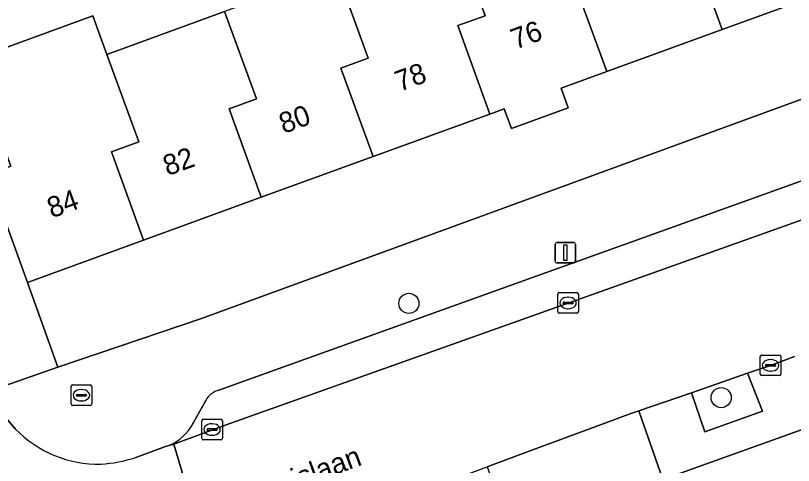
# Model space of a CAD drawing. Extents: x 162523 to 163266, y 381230 to 382050.
# Drawn here: x 162737.39 to 162775.21, y 381718.66 to 381740.55 of the extents above; entities that cross this region are included whole.
import ezdxf

# ---------------------------------------------------------------- set-up
doc = ezdxf.new("R2010")
doc.units = 0
for name, color, linetype in [('IMGEO_Boom', 7, 'Continuous'), ('IMGEO_Brandkraan', 7, 'Continuous'), ('IMGEO_Erf', 7, 'Continuous'), ('IMGEO_Groenvoorziening', 7, 'Continuous'), ('IMGEO_Kolk', 7, 'Continuous'), ('IMGEO_Lichtmast', 7, 'Continuous'), ('IMGEO_Openbare_ruimte_label', 7, 'Continuous'), ('IMGEO_Pand', 7, 'Continuous'), ('IMGEO_Pand_nummerreeks', 7, 'Continuous'), ('IMGEO_Parkeervlak_open', 7, 'Continuous'), ('IMGEO_Rijbaan_lokaal_open', 7, 'Continuous'), ('IMGEO_Voetpad_open', 7, 'Continuous')]:
    doc.layers.add(name, color=color, linetype=linetype)

msp = doc.modelspace()

# ---------------------------------------------------------------- linework, layer by layer
at = {"layer": 'IMGEO_Boom'}
for centre in [(162756.514, 381726.547), (162771.693, 381721.963)]:
    msp.add_circle(centre, 0.489, dxfattribs=at)
at = {"layer": 'IMGEO_Brandkraan'}
for p, q in [((162740.091, 381721.654), (162740.091, 381722.506)), ((162740.166, 381722.58), (162741.018, 381722.58)), ((162740.579, 381722.36), (162740.604, 381722.36)), ((162741.092, 381722.506), (162741.092, 381721.654)), ((162740.35, 381722.074), (162740.35, 381722.086)), ((162740.788, 381722.037), (162740.39, 381722.037)), ((162740.393, 381722.123), (162740.791, 381722.123)), ((162740.834, 381722.086), (162740.834, 381722.074)), ((162741.018, 381721.58), (162740.166, 381721.58)), ((162740.602, 381721.8), (162740.577, 381721.8))]:
    msp.add_line(p, q, dxfattribs=at)
for points in [[(162740.091, 381721.654), (162740.091, 381722.506)], [(162740.166, 381722.58), (162741.018, 381722.58)], [(162741.092, 381722.506), (162741.092, 381721.654)], [(162741.018, 381721.58), (162740.166, 381721.58)]]:
    msp.add_lwpolyline(points, dxfattribs=at)
for centre, radius, start, end in [((162740.168, 381722.504), 0.0765, 91.552, 178.448), ((162740.168, 381722.504), 0.0765, 91.552, 178.448), ((162741.016, 381722.504), 0.0765, 1.552, 88.448), ((162741.016, 381722.504), 0.0765, 1.552, 88.448), ((162740.39, 381722.083), 0.0403, 85.8775, 175.7526), ((162740.387, 381722.073), 0.0366, 178.938, 274.7102), ((162740.791, 381722.08), 0.043, 264.8664, 352.4533), ((162740.795, 381722.085), 0.0386, 1.7309, 96.639), ((162740.168, 381721.656), 0.0765, 181.552, 268.448), ((162740.168, 381721.656), 0.0765, 181.552, 268.448), ((162741.016, 381721.656), 0.0765, 271.552, 358.448), ((162741.016, 381721.656), 0.0765, 271.552, 358.448)]:
    msp.add_arc(centre, radius, start, end, dxfattribs=at)
for centre, major_axis, ratio, start_param, end_param in [((162740.578, 381722.08), (-0.387, 0.002), 0.722429, 4.712389, 7.853982), ((162740.603, 381722.08), (-0.39, 0.002), 0.717154, 1.570796, 4.712389)]:
    msp.add_ellipse(centre, major_axis=major_axis, ratio=ratio, start_param=start_param, end_param=end_param, dxfattribs=at)
at = {"layer": 'IMGEO_Erf'}
msp.add_lwpolyline([(162784.426, 381739.706), (162784.481, 381739.514), (162785.552, 381739.818), (162782.673, 381748.437), (162781.573, 381748.036), (162783.048, 381743.984), (162777.375, 381741.918), (162771.742, 381739.867), (162766.13, 381737.823), (162763.908, 381737.014), (162764.256, 381736.059), (162761.495, 381735.05), (162761.145, 381736.008), (162760.453, 381735.756), (162754.777, 381733.689), (162749.334, 381731.706), (162743.616, 381729.624), (162737.973, 381727.569), (162739.44, 381723.44), (162746.424, 381725.819)], close=True, dxfattribs=at)
for points in [[(162731.305, 381742.815), (162726.488, 381738.887), (162729.198, 381735.639), (162730.444, 381734.146), (162736.062, 381736.232), (162735.275, 381738.394), (162738.978, 381739.743), (162741.146, 381740.533), (162741.831, 381738.653), (162744.361, 381739.575), (162747.549, 381740.736)], [(162778.489, 381721.436), (162768.851, 381717.989), (162762.252, 381715.555), (162762.466, 381714.975), (162766.58, 381716.476), (162767.337, 381714.403), (162767.817, 381714.579), (162768.163, 381713.64), (162773.695, 381715.655), (162773.351, 381716.588), (162780.839, 381719.349)]]:
    msp.add_lwpolyline(points, dxfattribs=at)
at = {"layer": 'IMGEO_Groenvoorziening'}
msp.add_lwpolyline([(162770.249, 381722.202), (162770.895, 381720.292), (162773.711, 381721.304), (162772.973, 381723.146)], close=True, dxfattribs=at)
at = {"layer": 'IMGEO_Kolk'}
for p, q in [((162763.749, 381726.143), (162763.749, 381726.995)), ((162763.824, 381727.069), (162764.676, 381727.069)), ((162764.237, 381726.849), (162764.262, 381726.849)), ((162764.75, 381726.995), (162764.75, 381726.143)), ((162764.008, 381726.563), (162764.008, 381726.575)), ((162764.446, 381726.526), (162764.048, 381726.526)), ((162764.051, 381726.612), (162764.449, 381726.612)), ((162764.492, 381726.575), (162764.492, 381726.563)), ((162764.676, 381726.069), (162763.824, 381726.069)), ((162764.26, 381726.289), (162764.235, 381726.289)), ((162773.592, 381723.107), (162773.592, 381723.959)), ((162773.667, 381724.033), (162774.519, 381724.033)), ((162774.08, 381723.813), (162774.105, 381723.813)), ((162774.593, 381723.959), (162774.593, 381723.107)), ((162773.851, 381723.527), (162773.851, 381723.539)), ((162774.289, 381723.49), (162773.891, 381723.49)), ((162773.894, 381723.576), (162774.292, 381723.576)), ((162774.335, 381723.539), (162774.335, 381723.527)), ((162774.103, 381723.253), (162774.078, 381723.253)), ((162774.519, 381723.033), (162773.667, 381723.033)), ((162746.443, 381719.985), (162746.443, 381720.837)), ((162746.518, 381720.911), (162747.37, 381720.911)), ((162747.444, 381720.837), (162747.444, 381719.985)), ((162746.702, 381720.405), (162746.702, 381720.417)), ((162746.745, 381720.454), (162747.143, 381720.454)), ((162746.931, 381720.691), (162746.956, 381720.691)), ((162747.186, 381720.417), (162747.186, 381720.405)), ((162747.14, 381720.368), (162746.742, 381720.368)), ((162746.954, 381720.131), (162746.929, 381720.131)), ((162747.37, 381719.911), (162746.518, 381719.911))]:
    msp.add_line(p, q, dxfattribs=at)
for points in [[(162763.749, 381726.143), (162763.749, 381726.995)], [(162763.824, 381727.069), (162764.676, 381727.069)], [(162764.75, 381726.995), (162764.75, 381726.143)], [(162764.676, 381726.069), (162763.824, 381726.069)], [(162773.592, 381723.107), (162773.592, 381723.959)], [(162773.667, 381724.033), (162774.519, 381724.033)], [(162774.593, 381723.959), (162774.593, 381723.107)], [(162774.519, 381723.033), (162773.667, 381723.033)], [(162746.443, 381719.985), (162746.443, 381720.837)], [(162746.518, 381720.911), (162747.37, 381720.911)], [(162747.444, 381720.837), (162747.444, 381719.985)], [(162747.37, 381719.911), (162746.518, 381719.911)]]:
    msp.add_lwpolyline(points, dxfattribs=at)
for centre, radius, start, end in [((162763.826, 381726.993), 0.0765, 91.552, 178.448), ((162763.826, 381726.993), 0.0765, 91.552, 178.448), ((162764.674, 381726.993), 0.0765, 1.552, 88.448), ((162764.674, 381726.993), 0.0765, 1.552, 88.448), ((162764.048, 381726.572), 0.0403, 85.8775, 175.7526), ((162764.045, 381726.562), 0.0366, 178.938, 274.7102), ((162764.449, 381726.569), 0.043, 264.8664, 352.4533), ((162764.453, 381726.574), 0.0386, 1.7309, 96.639), ((162763.826, 381726.145), 0.0765, 181.552, 268.448), ((162763.826, 381726.145), 0.0765, 181.552, 268.448), ((162764.674, 381726.145), 0.0765, 271.552, 358.448), ((162764.674, 381726.145), 0.0765, 271.552, 358.448), ((162773.669, 381723.957), 0.0765, 91.552, 178.448), ((162773.669, 381723.957), 0.0765, 91.552, 178.448), ((162774.517, 381723.957), 0.0765, 1.552, 88.448), ((162774.517, 381723.957), 0.0765, 1.552, 88.448), ((162773.891, 381723.536), 0.0403, 85.8775, 175.7526), ((162773.888, 381723.526), 0.0366, 178.938, 274.7102), ((162774.292, 381723.533), 0.043, 264.8664, 352.4533), ((162774.296, 381723.538), 0.0386, 1.7309, 96.639), ((162773.669, 381723.109), 0.0765, 181.552, 268.448), ((162773.669, 381723.109), 0.0765, 181.552, 268.448), ((162774.517, 381723.109), 0.0765, 271.552, 358.448), ((162774.517, 381723.109), 0.0765, 271.552, 358.448), ((162746.52, 381720.835), 0.0765, 91.552, 178.448), ((162746.52, 381720.835), 0.0765, 91.552, 178.448), ((162747.368, 381720.835), 0.0765, 1.552, 88.448), ((162747.368, 381720.835), 0.0765, 1.552, 88.448), ((162746.742, 381720.414), 0.0403, 85.8775, 175.7526), ((162746.739, 381720.404), 0.0366, 178.938, 274.7102), ((162747.143, 381720.411), 0.043, 264.8664, 352.4533), ((162747.147, 381720.416), 0.0386, 1.7309, 96.639), ((162746.52, 381719.987), 0.0765, 181.552, 268.448), ((162746.52, 381719.987), 0.0765, 181.552, 268.448), ((162747.368, 381719.987), 0.0765, 271.552, 358.448), ((162747.368, 381719.987), 0.0765, 271.552, 358.448)]:
    msp.add_arc(centre, radius, start, end, dxfattribs=at)
for centre, major_axis, ratio, start_param, end_param in [((162764.236, 381726.569), (-0.387, 0.002), 0.722429, 4.712389, 7.853982), ((162764.261, 381726.569), (-0.39, 0.002), 0.717154, 1.570796, 4.712389), ((162774.079, 381723.533), (-0.387, 0.002), 0.722429, 4.712389, 7.853982), ((162774.104, 381723.533), (-0.39, 0.002), 0.717154, 1.570796, 4.712389), ((162746.93, 381720.411), (-0.387, 0.002), 0.722429, 4.712389, 7.853982), ((162746.955, 381720.411), (-0.39, 0.002), 0.717154, 1.570796, 4.712389)]:
    msp.add_ellipse(centre, major_axis=major_axis, ratio=ratio, start_param=start_param, end_param=end_param, dxfattribs=at)
at = {"layer": 'IMGEO_Lichtmast'}
for p, q in [((162763.72, 381729.512), (162764.51, 381729.512)), ((162764.51, 381729.512), (162763.72, 381729.512)), ((162763.62, 381728.612), (162763.62, 381729.412)), ((162763.62, 381729.412), (162763.62, 381728.612)), ((162764.61, 381729.412), (162764.61, 381728.612)), ((162764.61, 381728.612), (162764.61, 381729.412)), ((162764.51, 381728.512), (162763.72, 381728.512)), ((162763.72, 381728.512), (162764.51, 381728.512))]:
    msp.add_line(p, q, dxfattribs=at)
msp.add_lwpolyline([(162764.04, 381729.387), (162764.19, 381729.387), (162764.19, 381728.637), (162764.04, 381728.637), (162764.04, 381729.387)], dxfattribs=at)
for centre, start, end in [((162763.72, 381729.412), 90, 180), ((162763.72, 381729.412), 90, 180), ((162764.51, 381729.412), 0, 90), ((162764.51, 381729.412), 360, 90), ((162763.72, 381728.612), 180, 270), ((162763.72, 381728.612), 180, 270), ((162764.51, 381728.612), 270, 0), ((162764.51, 381728.612), 270, 0)]:
    msp.add_arc(centre, 0.1, start, end, dxfattribs=at)
at = {"layer": 'IMGEO_Pand'}
for points in [[(162771.742, 381739.867), (162777.375, 381741.918), (162775.809, 381746.217), (162777.137, 381746.701), (162775.935, 381750), (162775.589, 381750.949), (162772.971, 381750), (162769.956, 381748.898), (162771.504, 381744.65), (162770.176, 381744.166)], [(162771.742, 381739.867), (162770.176, 381744.166), (162771.504, 381744.65), (162769.956, 381748.898), (162764.344, 381746.854), (162765.892, 381742.606), (162764.564, 381742.122), (162766.13, 381737.823)], [(162766.13, 381737.823), (162764.564, 381742.122), (162765.892, 381742.606), (162764.344, 381746.854), (162758.667, 381744.787), (162760.215, 381740.539), (162758.887, 381740.055), (162760.453, 381735.756), (162761.145, 381736.008), (162761.495, 381735.05), (162764.256, 381736.059), (162763.908, 381737.014)], [(162752.991, 381742.72), (162754.539, 381738.472), (162753.211, 381737.988), (162754.777, 381733.689), (162760.453, 381735.756), (162758.887, 381740.055), (162760.215, 381740.539), (162758.667, 381744.787)], [(162747.549, 381740.736), (162749.096, 381736.49), (162747.768, 381736.006), (162749.334, 381731.706), (162754.777, 381733.689), (162753.211, 381737.988), (162754.539, 381738.472), (162752.991, 381742.72)], [(162742.05, 381733.923), (162743.378, 381734.407), (162741.831, 381738.653), (162741.146, 381740.533), (162738.978, 381739.743), (162735.275, 381738.394), (162736.062, 381736.232), (162737.16, 381733.217), (162736.062, 381732.817), (162737.973, 381727.569), (162743.616, 381729.624)], [(162747.549, 381740.736), (162744.361, 381739.575), (162741.831, 381738.653), (162743.378, 381734.407), (162742.05, 381733.923), (162743.616, 381729.624), (162749.334, 381731.706), (162747.768, 381736.006), (162749.096, 381736.49)]]:
    msp.add_lwpolyline(points, close=True, dxfattribs=at)
at = {"layer": 'IMGEO_Parkeervlak_open'}
for points in [[(162783.644, 381735.394), (162747.28, 381722.33)], [(162744.683, 381719.581), (162745.077, 381719.704), (162747.636, 381720.644), (162766.566, 381727.391), (162786.892, 381734.638)], [(162746.635, 381721.828), (162745.91, 381720.524)]]:
    msp.add_lwpolyline(points, dxfattribs=at)
for centre, radius, start, end in [((162747.555, 381721.311), 1.056, 105.1175, 150.6693), ((162743.969, 381721.78), 2.312, 287.9923, 327.0953)]:
    msp.add_arc(centre, radius, start, end, dxfattribs=at)
at = {"layer": 'IMGEO_Rijbaan_lokaal_open'}
for points in [[(162816.425, 381743.491), (162804.215, 381739.844), (162789.911, 381735.529), (162787.126, 381734.714), (162786.892, 381734.638), (162766.566, 381727.391), (162747.636, 381720.644), (162745.077, 381719.704), (162746.861, 381713.692), (162748.15, 381714.148), (162751.373, 381715.289), (162757.781, 381717.663), (162760.315, 381718.601), (162762.482, 381719.404), (162766.087, 381720.739), (162767.355, 381721.2), (162767.683, 381721.314), (162770.249, 381722.202), (162772.973, 381723.146), (162774.09, 381723.533), (162775.256, 381723.963)], [(162737.39, 381720.437), (162735.869, 381722.192), (162735.076, 381723.106), (162731.988, 381720.709), (162733.045, 381719.334)], [(162745.077, 381719.704), (162744.683, 381719.581), (162743.232, 381719.055)], [(162744.3, 381712.723), (162745.607, 381713.218), (162746.861, 381713.692), (162745.077, 381719.704)]]:
    msp.add_lwpolyline(points, dxfattribs=at)
for centre, radius, start, end in [((162741.418, 381724.331), 5.602, 224.0344, 271.1901), ((162741.147, 381725.35), 6.632, 273.3458, 288.3251)]:
    msp.add_arc(centre, radius, start, end, dxfattribs=at)
at = {"layer": 'IMGEO_Voetpad_open'}
for points in [[(162886.293, 381769.608), (162880.883, 381768.073), (162819.558, 381750.008), (162818.005, 381749.551), (162817.893, 381749.518), (162788.827, 381740.956), (162788.882, 381740.764), (162788.153, 381740.557), (162785.552, 381739.818), (162784.481, 381739.514), (162784.426, 381739.706), (162746.424, 381725.819), (162739.44, 381723.44), (162735.869, 381722.192), (162737.39, 381720.437)], [(162719.251, 381743.697), (162728.038, 381733.186), (162727.299, 381732.493), (162734.001, 381724.355), (162735.076, 381723.106), (162735.869, 381722.192), (162739.44, 381723.44), (162737.973, 381727.569), (162736.062, 381732.817), (162737.16, 381733.217), (162736.062, 381736.232), (162730.444, 381734.146), (162729.198, 381735.639), (162726.488, 381738.887), (162724.481, 381741.349)], [(162747.28, 381722.33), (162783.644, 381735.394)], [(162775.256, 381723.963), (162774.09, 381723.533), (162772.973, 381723.146), (162773.711, 381721.304), (162770.895, 381720.292), (162770.249, 381722.202), (162767.683, 381721.314), (162768.851, 381717.989), (162778.489, 381721.436), (162783.015, 381723.019)], [(162745.91, 381720.524), (162746.635, 381721.828)], [(162743.232, 381719.055), (162744.683, 381719.581)]]:
    msp.add_lwpolyline(points, dxfattribs=at)
msp.add_lwpolyline([(162762.482, 381719.404), (162760.315, 381718.601), (162761.006, 381716.713), (162761.529, 381715.288), (162762.252, 381715.555), (162768.851, 381717.989), (162767.683, 381721.314), (162767.355, 381721.2), (162766.087, 381720.739)], close=True, dxfattribs=at)
for centre, radius, start, end in [((162747.555, 381721.311), 1.056, 105.1175, 150.6693), ((162741.418, 381724.331), 5.602, 224.0344, 271.1901), ((162743.969, 381721.78), 2.312, 287.9923, 327.0953), ((162741.147, 381725.35), 6.632, 273.3458, 288.3251)]:
    msp.add_arc(centre, radius, start, end, dxfattribs=at)

# ---------------------------------------------------------------- texts
at = {"layer": 'IMGEO_Openbare_ruimte_label'}
msp.add_text('Thomas à Kempislaan', height=1, rotation=20.2475, dxfattribs=at).set_placement((162741.806, 381714.101))
at = {"layer": 'IMGEO_Pand_nummerreeks'}
for s, rotation, p in [('76', 20.0101, (162761.689, 381738.888)), ('78', 20.0101, (162756.058, 381736.837)), ('80', 20.0101, (162750.424, 381734.786)), ('82', 20.0101, (162744.783, 381732.732)), ('84', 20.0077, (162739.152, 381730.681))]:
    msp.add_text(s, height=1, rotation=rotation, dxfattribs=at).set_placement(p)

doc.saveas('drawing.dxf')
